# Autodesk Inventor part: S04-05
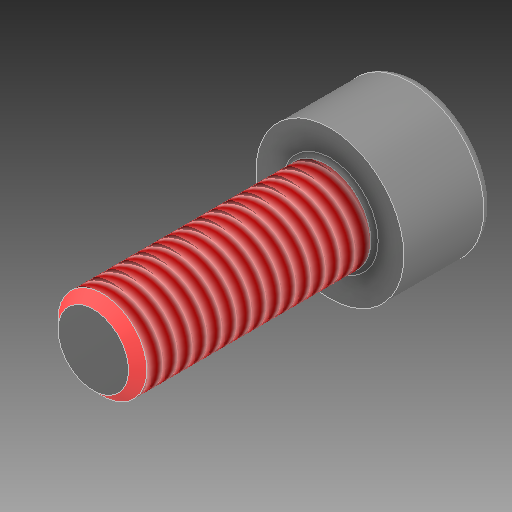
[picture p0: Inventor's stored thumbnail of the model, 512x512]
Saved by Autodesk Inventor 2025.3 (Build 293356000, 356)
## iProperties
Manager: ISO 4762 (DIN 912)
Created: 2025-05
Part Number: S04-05
Material: Všeobecné
Document SubType Name: Modeling
Designer: Patrik
Density: 1 g/cm^3
Appearance: Výchozí
Description: Imbusový šroub s válcovou hlavou
Stock Number: E 1200/6x16
Mass: 0.853299 g
Surface Area: 6.8161 cm^2
Volume: 0.853299 cm^3
User Status: 12.9
Sending System: KiM GmbH
Major Version: 4.0
Minor Version: 0.0
Format Version: 0.0
Product Id: KiM GmbH
cc_prop_force_one_body: 1
Hersteller: Meusburger
Material: 12.9 ISO 4762 (DIN 912)
Bestellnummer: E 1200/6x16
Teilenummer: E 1200/6x16
Beschreibung: Zylinderkopfschraube mit Innensechskant _ Cylinder head screw with hexagon socket
Author: Patrik
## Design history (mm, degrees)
feature "E 1200_6x16_1_1:1"
feature "Závit1" dims "d0" = 25, "d1" = 0
node "Těleso1"
